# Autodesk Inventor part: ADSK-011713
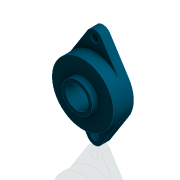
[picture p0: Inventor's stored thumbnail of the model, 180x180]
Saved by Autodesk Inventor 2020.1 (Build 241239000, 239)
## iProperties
Created: 1999-11
Part Number: ADSK-011713
Material: Acier doux
Document SubType Name: Modeling
Designer: cmcgourin
Density: 7.86 g/cm^3
Appearance: Bearing Blue
Mass: 2253.05 g
Surface Area: 415.881 cm^2
Volume: 286.648 cm^3
Control State: 0
Master: False
Checked Out: False
Shininess: 0.0
Length Units: 11269
Angle Units: 11279
Time Units: 11290
Mass Units: 11283
Length Display Precision: 3
Angle Display Precision: 2
Compacted: True
Dimensions: 104,8x171,5x44,4 mm
Mass: 2,253 kg
Density: 0.0
Volumn: 0.0
Area: 0.0
PropertySet Name: Model Information
Author: cmcgourin
Revision Number: -
Title: ADSK-011713
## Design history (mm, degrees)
node "Solide1"
  node "Extrusion1" dims "d8" = 14.2875 (= H), "d9" = 0
  node "Extrusion2" dims "d10" = 20.21875 (= -H + C - JAY), "d11" = 0
  node "Extrusion3" dims "d13" = 9.92188, "d14" = 0
  node "Hole1" dims "d15" = 38.1 (= SS), "d16" = 9.525, "d17" = 6.35, "d18" = 60 deg, "d19" = 19.05, "d20" = 118 deg
  node "Extrusion4" dims "d30" = 5.01538 (= C - A), "d31" = 0
sketch "Sketch1"
  geometry: L1 (-44.194, -28.131)-(-11.578, -79.37); L2 (44.194, -28.131)-(11.578, -79.37); L3 (11.578, 79.37)-(44.194, 28.131); L4 (-11.578, 79.37)-(-44.194, 28.131); L5 (0, 72)-(0, -72); L6 (-43.139, 85.725)-(46.118, 85.725); L7 (-46.512, -85.725)-(48.244, -85.725); C1 r 6.747 at (0, 72); C2 r 6.747 at (0, -72); A1 r 52.388 centre (0, 0) between (-44.194, -28.131) and (44.194, -28.131); A2 r 13.725 centre (0, 72) between (11.578, 79.37) and (-11.578, 79.37); A3 r 13.725 centre (0, -72) between (-11.578, -79.37) and (11.578, -79.37); 1 further point
  constraints: 14 end point, 9 tangent, 8 point on circle, 5 centre point, 2 concentric, 2 equal radius, 2 parallel, 2 point on line, 1 coincident, 1 midpoint, 1 perpendicular, 1 vertical
  dimensions: "d0" = 104.775 diameter of A1 (= M); "d6" = 13.49375 diameter of C1 (computed from F); "d22" = 144 distance of A3.centre A2.centre; "d27" = 85.725 distance from line of L6 A1.centre (= 0.5 x B); "d28" = 171.45 distance between parallel lines of L7 L6 (= B)
node "Corps solides"
node "Corps surfaciques"
sketch "Sketch2"
  geometry: C1 r 52.387 at (0, 0); A1 r 52.388 centre (0, 0) between (-44.229, 28.075) and (-44.194, -28.131) reference
  constraints: 1 centre point, 1 coincident
  dimensions: "d21" = 104.775 diameter of C1 (= M)
sketch "Sketch3"
  geometry: C1 r 25.995 at (0, 0); C2 r 52.387 at (0, 0) reference
  constraints: 1 centre point, 1 concentric
  dimensions: "d12" = 51.99063 diameter of C1 (= L)
sketch "Sketch4"
  geometry: 1 further point
sketch "Sketch5"
  geometry: C1 r 19.05 at (0, 0) reference; C2 r 39.291 at (0, 0); A1 r 52.388 centre (0, 0) between (-44.229, 28.075) and (-44.194, -28.131) reference
  constraints: 1 centre point, 1 coincident
  dimensions: "d29" = 78.58125 diameter of C2 (= 0.75 x M)
other parameters: "A" = 42.98462 [user parameter; used in 1 equation term], "B" = 171.45 [user parameter; used in 2 equation terms], "C" = 48 [user parameter; used in 2 equation terms], "D" = 143.66875 [user parameter], "F" = 12.7 [user parameter; used in 1 equation term], "H" = 14.2875 [user parameter; used in 2 equation terms], "JAY" = 13.49375 [user parameter; used in 1 equation term], "L" = 51.99063 [user parameter; used in 1 equation term], "M" = 104.775 [user parameter; used in 3 equation terms], "N_1" = 46.43438 [user parameter], "SS" = 38.1 [user parameter; used in 1 equation term]
